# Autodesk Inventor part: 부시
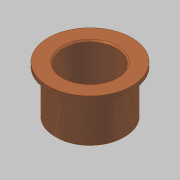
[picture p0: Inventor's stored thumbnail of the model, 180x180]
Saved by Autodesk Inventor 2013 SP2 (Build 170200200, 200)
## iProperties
Created: 2013-06
Part Number: 부시
Document SubType Name: Modeling
Designer: SeoGD™[esajin.kr]
Density: 1 g/cm^3
Material: 일반
Mass: 31.4212 g
Surface Area: 129.264 cm^2
Volume: 31.4212 cm^3
Author: SeoGD™[esajin.kr]
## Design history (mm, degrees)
sketch "스케치1"
  geometry: C1 r 31 at (0, 0) reference; C2 r 25 at (0, 0) reference; C3 r 30 at (0, 0) reference; 1 further point
  node "참조1"
  node "참조2"
  node "참조4"
extrude "돌출1" new body sketch "스케치1" distance "d0" = 3; taper "d1" = 0 deg
extrude "돌출2" join sketch "스케치1" distance "d2" = 35; taper "d3" = 0 deg
chamfer "모따기1" distance "d6" = 1; stored, may be unused: second distance "d7" = 2, angle "d8" = 45 deg
sketch "스케치3"
  geometry: C1 r 19 at (0, 0); 1 further point
  constraints: 1 centre point, 1 coincident
  dimensions: "d13" = 38 diameter of C1
extrude "돌출4" cut sketch "스케치3" stored distance "d14" = 10; taper "d15" = 0 deg
chamfer "모따기3" distance "d16" = 1; stored, may be unused: second distance "d17" = 2, angle "d18" = 45 deg
node "솔리드1"
